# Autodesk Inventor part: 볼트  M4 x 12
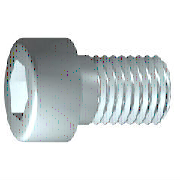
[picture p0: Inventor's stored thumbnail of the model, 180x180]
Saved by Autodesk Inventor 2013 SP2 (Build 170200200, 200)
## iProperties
IsCustomPart: 0
Created: 2015-12
Part Number: 볼트  M4 x 12
Material: 스테인리스강
Description: 6각머리 태핑 나사
Document SubType Name: Modeling
Standard: KS B 1003
Designer: mdu
Standards Organization: KS
Language: ko-KR
Size Designation: M 4 x 12
Categories: <MemberInstance><Categories><Category DisplayName="조임쇠" InternalName="e4da775c-781d-43d5-af7c-5136215cf5a6" Mnemonic="FSTN"><Category DisplayName="볼트" InternalN
Density: 8.08 g/cm^3
Mass: 2.29719 g
Surface Area: 3.30853 cm^2
Volume: 0.284306 cm^3
Author: mdu
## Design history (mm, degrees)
sketch "스케치1"
  geometry: L1 (-1, 0)-(12, 0); L2 (12, 0)-(12, 2); L3 (12, 2)-(1.75, 2); L4 (1.75, 2)-(1.32, 2); L5 (1.32, 2)-(0, 2); L6 (0, 2)-(0, 3.5); L7 (0, 3.5)-(-4, 3.5); L8 (-4, 3.5)-(-4, 1.732); L9 (-4, 1.732)-(-2, 1.732); L10 (-2, 1.732)-(-1, 0); L11 (-7.2, 0)-(15.2, 0) reference; L12 (0, -0.7)-(0, 4.2) reference; L13 (1.75, 2)-(0, 2)
  constraints: 22 end point, 6 parallel, 2 collinear, 2 perpendicular, 1 horizontal, 1 point on line
  dimensions: "d1" = 10.25 distance from line of L3.end L2 (= GEL); "d2" = 0.42952 distance of L4.end L3.end (computed from GAL); "d3" = 4 distance between parallel lines of L8 L6 (= KOH); "d4" = 2 distance of L8.end L9.end (= INTI); "d5" = 60 deg angle of L10 L1; "d6" = 4 diameter of L3 L1 (= GD); "d7" = 4 diameter of L5 L1 (= BDM); "d8" = 3.4641 diameter of L9 L1 (= 1.1547 x SW); "d9" = 7 diameter of L7 L1 (= KOD); "d26" = 12 distance between parallel lines of L12 L2 (= NLG)
revolve "본체" sketch "스케치1" stored, may be unused: angle "d10" = 90 deg
sketch "스케치2"
  geometry: L1 (0, -4.9)-(0, 4.9) reference; L2 (-4.9, 0)-(4.9, 0) reference; L3 (1.732, 0)-(0.866, -1.5); L4 (0.866, -1.5)-(-0.866, -1.5); L5 (-0.866, -1.5)-(-1.732, 0); L6 (-1.732, 0)-(-0.866, 1.5); L7 (-0.866, 1.5)-(0.866, 1.5); L8 (0.866, 1.5)-(1.732, 0); 2 further points
  constraints: 12 end point, 1 coincident, 1 horizontal alignment, 1 point on line, 12 other
extrude "슬롯" join sketch "스케치2" stored distance "d11" = 10; taper "d12" = 0 deg
workplane "Work Plane1"
fillet "Fillet2" dims "d30" = 0.1 (= R)
body "Solid1"
fillet "모깎기1" dims "d17" = 0.4 (= RR)
feature "스레드" dims "d13" = 10.25 (= GEL), "d14" = 0
chamfer "모따기1" distance "d15" = 0.42941 (= -0.5 x SPD + 0.5 x GD); stored, may be unused: second distance "d16" = 0.42941 (= GUL), angle "d27" = 45 deg
other parameters: "GD" = 4 (= NND) [user parameter; used in 2 equation terms], "NLG" = 12 [user parameter; used in 1 equation term], "GEL" = 10.25 [user parameter; used in 2 equation terms], "KOD" = 7 [user parameter; used in 1 equation term], "KOH" = 4 [user parameter; used in 1 equation term], "INTI" = 2 [user parameter; used in 1 equation term], "GAL" = 0.42941 (= 0.61345 x PTC) [user parameter; used in 1 equation term], "GUL" = 0.42941 (= 0.61345 x PTC) [user parameter; used in 1 equation term], "BDM" = 4 (= NND) [user parameter; used in 1 equation term], "SW" = 3 [user parameter; used in 2 equation terms], "RR" = 0.4 [user parameter; used in 1 equation term], "SPD" = 3.14117 (= NND - 1.2269 x PTC) [user parameter; used in 1 equation term], "d19" = 0, "d28" = 0, "d29" = 0, "R" = 0.1 [user parameter; used in 1 equation term], "PHH" = 0.2 [user parameter], "GD1" = 3.14117 (= THREADDIA - 1.2269 x PTC) [user parameter], "THREADDIA" = 4 [user parameter; used in 1 equation term], "FAWI" = 45 deg [user parameter], "TPU" = 14.28571 (computed from PTC) [user parameter], "PTC" = 0.7 [user parameter; used in 5 equation terms], "NND" = 4 [user parameter; used in 3 equation terms], "TOA" = 30 deg [user parameter], "E0" = 3.465 (= 1.155 x SW) [user parameter]
